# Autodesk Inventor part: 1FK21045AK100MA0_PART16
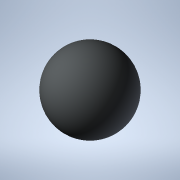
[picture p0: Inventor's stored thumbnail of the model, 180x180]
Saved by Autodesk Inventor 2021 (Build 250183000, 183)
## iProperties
Created: 2025-04
Part Number: 1FK21045AK100MA0_PART16
Material: Generic
Catalog Web Link: www.3dfindit.com
Description: -Servo synchronous motor
Document SubType Name: Modeling
Designer: psAdmin
Mass: 0.137258 g
Surface Area: 1.2868 cm^2
Volume: 0.137258 cm^3
Density: 1 g/cm^3
Appearance: PSOLRGB-212-217-219
Category: PARTsolutions
Title: 1FK21045AK100MA0_PART16
Author: Cadenas PARTsolutions
Comments: Servo synchronous motor
Sending System: PARTsolutions
Preprocessor: ST-DEVELOPER v19.3
PSOL_IDENT_0: {$CADENAS_DATA/23d-libs/siemens_ag/_cat_/e0/5f/1fk21045ak100ma0.prj},216 {VTYP=3D},{NB=1FK21045AK100
PSOL_IDENT_1: MA0_PART16},{LINA=1FK21045AK100MA0_PART16},{NN=1FK21045AK100MA0_PART16},{NOPRJ=TRUE},{DATE=19.08.202
PSOL_IDENT_2: 5 14:01:03},{GEOMDATE=30.07.2025 02:01:57},{VERSION=},{LINEID=10},{WBVAR=},{WBNUMERIC=}  {NB=1FK2104
PSOL_IDENT_3: 5AK100MA0_PART16},{LINA=1FK21045AK100MA0_PART16},{KT=DUMMY},{PREVIEW=../../../_pool_/0f/2c/p_d211_xx
PSOL_IDENT_4: _00438j.png},{DESCSHORT=SIMOTICS S-1FK2 HD, SINAMICS S210 3AC 400V-480V, 1.7 Nm, 6000 rpm},{DESCLONG=
PSOL_IDENT_5: SIMOTICS S-1FK2 HD servo motor M0=2.4 Nm; PN = 1.07 kW at nN=6000 rpm (380-480 V); PN = 0.75 kW at n
PSOL_IDENT_6: N=3000 rpm (200-240 V); with holding brake; degree of protection IP64; cylindrical shaft D19x40mm; a
PSOL_IDENT_7: bsolute encoder 22-bit + 12-bit multiturn (encoder AM22DQC); with OCC interface; plug size M17, rota
PSOL_IDENT_8: table; SIMOTICS S-1FK2 servomotorfor a wide range of uses in industrial environments. SIMOTICS S‑1FK
PSOL_IDENT_9: 2 servomotors are compact synchronous motors with a high dynamic performance that set themselves apa
PSOL_IDENT_10: rt as a result of their high power density, degree of protection and overload capability. The motors
PSOL_IDENT_11: are available in two variants: as High Dynamic variant (highest dynamic performance as a result of
PSOL_IDENT_12: the low intrinsic moment of inertia for applications demanding a high dynamic performance with low m
PSOL_IDENT_13: oved masses) - and as Compact variant (precise and stable closed-loop control for medium up to large
PSOL_IDENT_14: moved masses as a result of a medium intrinsic moment of inertia). SIMOTICSS‑1FK2 servomotors fully
PSOL_IDENT_15: exploit their strengths in a system with the SINAMICSS210 frequency converter and simple connection
PSOL_IDENT_16: using the one cable connection (OCC). Advantages include the short control and positioning times, f
PSOL_IDENT_17: ast and precise correction of disturbing quantities as well as stable control with a high dynamic pe
PSOL_IDENT_18: rformance. The servo motors can be configured to address a wide range of requirements. For example w
PSOL_IDENT_19: ith and without holding brake, IP64 or IP65 degree of protection, singleturn or multiturn absolute e
PSOL_IDENT_20: ncoders - to name just a few. Further, the servomotors are available in different shaft heights exte
PSOL_IDENT_21: nding from 20 to 100. A shaft sealing ring is available to achieve an IP65 degree of protection and
PSOL_IDENT_22: for subsequent mounting at the motor or as spare part. SIMOTICS - the optimum motor for each and eve
PSOL_IDENT_23: ry motion control application.},{INTNO=804766807114},{SUPPLIERALTNO=1FK2104-5AK10-0MA0},{MANUID=1FK2
PSOL_IDENT_24: 1045AK100MA0},{MANUNAME=Siemens},{MANUTYPEDESC=Synchronous motor 1FK2-HD 2,39 Nm},{AAU732=SIMOTICS},
PSOL_IDENT_25: {AAO057=S-1FK2},{AAU734=SIMOTICS S-1FK2 HD servo motor M0=2.4 Nm; PN = 1.07 kW at nN=6000 rpm (380-4
PSOL_IDENT_26: 80 V); PN = 0.75 kW at nN=3000 rpm (200-240 V); with holding brake; degree of protection IP64; cylin
PSOL_IDENT_27: drical shaft D19x40mm; absolute encoder 22-bit + 12-bit multiturn (encoder AM22DQC); with OCC interf
PSOL_IDENT_28: ace; plug size M17, rotatable;},{AAW338=Synchronous motor 1FK2-HD 2,39 Nm},{AAO742=SIMOTICS},{AAO663=
PSOL_IDENT_29: 4042948691236},{NOCUPEROU=1},{PRICEQUANTITY=1},{QUANTITYMIN=1},{QUANTITYINT=1},{CTN=85015100},{COO=D
PSOL_IDENT_30: E},{AAO676=1FK2104-5AK10-0MA0},{AAO677=Siemens AG},{ORDERUNIT=C62},{CONTENTUNIT=C62}
NB: 1FK21045AK100MA0_PART16
NT: Servo synchronous motor
NBSYN: $MANUID._PART16
LINA: 1FK21045AK100MA0_PART16
CATALOG: SIEMENS
PREVIEW: ../../../_pool_/0f/2c/p_d211_xx_00438j.png
DESCSHORT: SIMOTICS S-1FK2 HD, SINAMICS S210 3AC 400V-480V, 1.7 Nm, 6000 rpm
DESCLONG: SIMOTICS S-1FK2 HD servo motor M0=2.4 Nm; PN = 1.07 kW at nN=6000 rpm (380-480 V); PN = 0.75 kW at nN=3000 rpm (200-240 V); with holding brake; degree of protec
INTNO: 804766807114
SUPPLIERALTNO: 1FK2104-5AK10-0MA0
MANUID: 1FK21045AK100MA0
MANUNAME: Siemens
MANUTYPEDESC: Synchronous motor 1FK2-HD 2,39 Nm
AAU732: SIMOTICS
AAO057: S-1FK2
AAU734: SIMOTICS S-1FK2 HD servo motor M0=2.4 Nm; PN = 1.07 kW at nN=6000 rpm (380-480 V); PN = 0.75 kW at nN=3000 rpm (200-240 V); with holding brake; degree of protec
AAW338: Synchronous motor 1FK2-HD 2,39 Nm
AAO742: SIMOTICS
AAO663: 4042948691236.0
NOCUPEROU: 1
PRICEQUANTITY: 1
QUANTITYMIN: 1
QUANTITYINT: 1
CTN: 85015100
COO: DE
ARTICLENO: 1FK21045AK100MA0_PART16
BOMINFO: 1FK21045AK100MA0_PART16
CREATOR: CADENAS GmbH
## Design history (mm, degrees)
feature "2025_04_17_15_45_15_0090"
body "Solid1"
